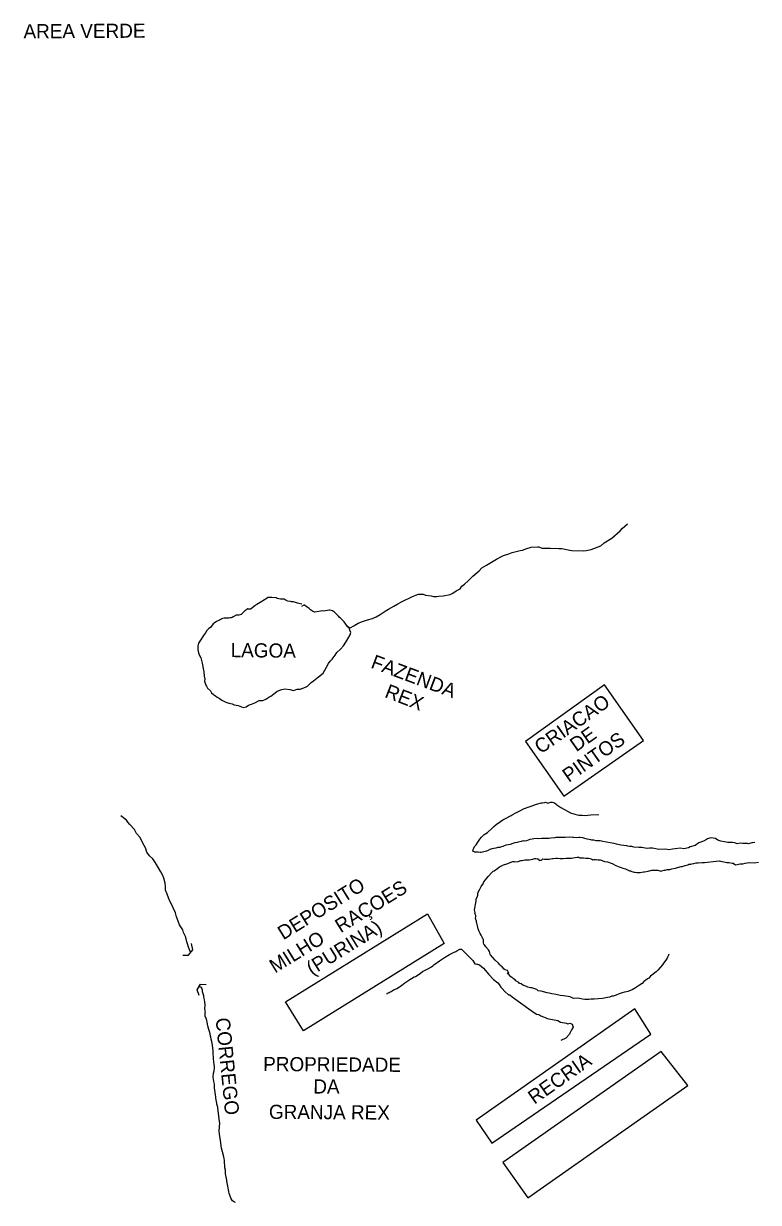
# Model space of a CAD drawing. Extents: x 325899 to 363134, y 7578590 to 7592502.
# Drawn here: x 339067.3 to 339275, y 7582028.3 to 7582361.5 of the extents above; entities that cross this region are included whole.
import ezdxf

# ---------------------------------------------------------------- set-up
doc = ezdxf.new("R2010")
doc.units = 0
for name, color, linetype in [('EDIFEXISTENT', 7, 'Continuous'), ('EDIFIDENTIF', 7, 'Continuous'), ('EDIFOBRAEXIS', 7, 'Continuous')]:
    doc.layers.add(name, color=color, linetype=linetype)

msp = doc.modelspace()

# ---------------------------------------------------------------- linework, layer by layer
at = {"layer": 'EDIFEXISTENT'}
for p, q in [((339231.45, 7582174.59), (339209.14, 7582158.63)), ((339242.46, 7582158.88), (339231.45, 7582174.59)), ((339209.14, 7582158.63), (339220.01, 7582143.13)), ((339220.01, 7582143.13), (339242.46, 7582158.88)), ((339141.27, 7582085.01), (339181.42, 7582109.92)), ((339181.42, 7582109.92), (339186.17, 7582101.54)), ((339113.87, 7582098.24), (339115.06, 7582099.76)), ((339115.06, 7582099.76), (339114.68, 7582101.48)), ((339186.17, 7582101.54), (339146.34, 7582076.83)), ((339112.23, 7582098.19), (339113.87, 7582098.24)), ((339116.31, 7582088.39), (339117.31, 7582090.01)), ((339117.31, 7582090.01), (339118.91, 7582089.96)), ((339116.9, 7582086.81), (339116.31, 7582088.39)), ((339146.34, 7582076.83), (339141.27, 7582085.01)), ((339240.02, 7582083.01), (339195.18, 7582051.55)), ((339244.54, 7582075.84), (339240.02, 7582083.01)), ((339199.58, 7582045.05), (339244.54, 7582075.84)), ((339247.52, 7582071.03), (339202.76, 7582039.63)), ((339255.01, 7582061.35), (339247.52, 7582071.03)), ((339209.78, 7582029.63), (339255.01, 7582061.35)), ((339195.18, 7582051.55), (339199.58, 7582045.05)), ((339202.76, 7582039.63), (339209.78, 7582029.63))]:
    msp.add_line(p, q, dxfattribs=at)
at = {"layer": 'EDIFOBRAEXIS'}
for points in [[(339158.77, 7582191.23), (339159.32, 7582190.71), (339159.6, 7582190.71), (339160.6, 7582191.33), (339160.88, 7582191.51), (339161.85, 7582192.08), (339163.02, 7582192.53), (339164.5, 7582192.99), (339165.93, 7582193.41), (339166.9, 7582193.83), (339168.03, 7582194.48), (339169.49, 7582195.48), (339170.41, 7582196), (339171.87, 7582196.88), (339173.09, 7582197.55), (339174.04, 7582198.05), (339175.04, 7582198.55), (339176.24, 7582199.14), (339177.16, 7582199.56), (339178.18, 7582199.99), (339178.87, 7582200.21), (339180.21, 7582200.24), (339180.82, 7582199.96), (339182.5, 7582199.76), (339183.08, 7582199.6), (339184.04, 7582199.54), (339184.55, 7582199.66), (339185.88, 7582199.75), (339187.86, 7582200.16), (339188.55, 7582200.56), (339189.53, 7582201.16), (339190.62, 7582201.73), (339191.17, 7582202.54), (339191.88, 7582203.06), (339192.94, 7582204.02), (339193.94, 7582205.02), (339194.27, 7582205.37), (339195.5, 7582206.33), (339196.04, 7582206.8), (339196.81, 7582207.68), (339198.12, 7582208.41), (339200.91, 7582210.1), (339202.34, 7582210.93), (339202.93, 7582211.18), (339204.43, 7582211.62), (339205.4, 7582212.04), (339207.64, 7582212.55), (339208.26, 7582212.69), (339209.53, 7582213.14), (339210.42, 7582213.46), (339210.7, 7582213.53), (339212.61, 7582213.64), (339212.87, 7582213.58), (339213.75, 7582213.27), (339215.73, 7582213.27), (339216.24, 7582213.22), (339218.58, 7582213.19), (339219.42, 7582213.15), (339221.65, 7582212.72), (339222.21, 7582212.59), (339225.51, 7582212.48), (339226.27, 7582212.57), (339227.68, 7582212.91), (339230.41, 7582213.9), (339231.41, 7582214.73), (339233.5, 7582216.08), (339235.92, 7582218.16), (339236.43, 7582218.79), (339237.95, 7582220.14)], [(339145.92, 7582197.37), (339144.71, 7582197.66), (339144.12, 7582197.87), (339143.52, 7582198.05), (339143.01, 7582198.11), (339142.75, 7582198.19), (339141.99, 7582198.3), (339141.46, 7582198.48), (339140.91, 7582198.82), (339139.84, 7582198.83), (339138.98, 7582199.04), (339138.67, 7582199.17), (339137.4, 7582199.34), (339136.41, 7582199.33), (339135.62, 7582198.8), (339135.36, 7582198.63), (339134.16, 7582197.9), (339133.16, 7582197.35), (339132.86, 7582197.1), (339132.6, 7582196.93), (339132.27, 7582196.7), (339131.62, 7582196.05), (339131.37, 7582196.03), (339130.86, 7582196.01), (339130.61, 7582196.06), (339130.05, 7582195.68), (339129.79, 7582195.51), (339129.25, 7582194.93), (339128.74, 7582194.5), (339128.15, 7582194.33), (339127.59, 7582194.26), (339127.31, 7582194.27), (339126.72, 7582193.94), (339126.19, 7582193.67), (339125.93, 7582193.57), (339125.62, 7582193.52), (339125.32, 7582193.47), (339124.73, 7582193.48), (339124, 7582193.49), (339123.49, 7582193.34), (339122.93, 7582193.12), (339122.67, 7582192.89), (339121.78, 7582192.47), (339121.11, 7582192.02), (339120.83, 7582191.9), (339120.13, 7582190.86), (339119.59, 7582190.51), (339118.95, 7582189.91), (339118.74, 7582189.38), (339118.33, 7582188.82), (339117.89, 7582188.27), (339117.45, 7582187.51), (339117.24, 7582187.21), (339116.7, 7582186.4), (339116.52, 7582185.59), (339116.48, 7582184.63), (339116.67, 7582183.63), (339116.92, 7582183.07), (339117.34, 7582182.28), (339117.54, 7582181.49), (339117.71, 7582180.7), (339118.14, 7582178.79), (339118.24, 7582178.25), (339118.33, 7582177.03), (339118.45, 7582176.19), (339118.41, 7582175.61), (339118.81, 7582174.56), (339118.96, 7582174.28), (339119.23, 7582173.69), (339120.06, 7582172.9), (339120.39, 7582172.38), (339120.94, 7582171.89), (339121.47, 7582171.51), (339121.97, 7582171.17), (339122.55, 7582170.81), (339123.31, 7582170.29), (339123.84, 7582169.96), (339124.4, 7582169.72), (339125.23, 7582169.43), (339126.22, 7582169.27), (339126.8, 7582169.01), (339127.94, 7582168.74), (339129.29, 7582168.24), (339130.13, 7582168.36), (339130.87, 7582168.86), (339131.71, 7582169.13), (339132.58, 7582169.56), (339133.88, 7582170.23), (339134.85, 7582170.19), (339135.74, 7582170.54), (339136.59, 7582171.14), (339137.12, 7582171.46), (339138.38, 7582172.39), (339138.97, 7582172.84), (339140.24, 7582173.26), (339141.09, 7582173.5), (339142.56, 7582173.26), (339143.55, 7582172.97), (339144.62, 7582173.36), (339145.43, 7582173.38), (339146.96, 7582174), (339147.47, 7582174.27), (339148.53, 7582175.25), (339149.19, 7582175.78), (339150.6, 7582176.91), (339151.91, 7582177.93), (339152.87, 7582179.65), (339153.41, 7582180.61), (339153.95, 7582181.27), (339154.44, 7582181.87), (339155.32, 7582183.03), (339155.84, 7582183.76), (339156.84, 7582184.67), (339157.71, 7582185.65), (339158.39, 7582186.63), (339158.9, 7582187.62), (339159.6, 7582188.78), (339159.79, 7582189.41), (339159.52, 7582190.1), (339159.27, 7582190.69), (339158.77, 7582191.23), (339158.39, 7582191.76), (339157.84, 7582192.41), (339157.39, 7582192.89), (339156.93, 7582193.38), (339156.46, 7582193.77), (339156.28, 7582194.05), (339155.58, 7582194.64), (339155.15, 7582195.18), (339154.57, 7582195.54), (339153.94, 7582195.7), (339153.68, 7582195.73), (339153.12, 7582195.63), (339152.03, 7582195.44), (339151.65, 7582195.52), (339150.75, 7582195.33), (339150.12, 7582195.21), (339149.46, 7582195.19), (339148.93, 7582195.45), (339148.4, 7582195.84), (339147.89, 7582196.3), (339147.14, 7582196.77), (339146.68, 7582197.13), (339146.43, 7582197.16), (339145.81, 7582196.76)], [(339273.96, 7582130.06), (339273.33, 7582129.96), (339273.07, 7582129.97), (339272.18, 7582129.72), (339271.92, 7582129.75), (339270.93, 7582129.76), (339270.55, 7582129.79), (339269.82, 7582129.88), (339268.93, 7582129.68), (339268.27, 7582129.94), (339267.68, 7582130.05), (339266.29, 7582130.02), (339265.35, 7582130.26), (339264.33, 7582130.42), (339263.47, 7582130.68), (339262.87, 7582131.15), (339261.47, 7582131.37), (339260.53, 7582131.12), (339260.27, 7582130.92), (339259.45, 7582130.42), (339258.08, 7582129.93), (339257.05, 7582129.25), (339255.72, 7582128.79), (339255.21, 7582128.59), (339253.91, 7582128.25), (339252.85, 7582128.44), (339251.47, 7582128.22), (339250.66, 7582128.21), (339249.69, 7582128.01), (339248.81, 7582128.15), (339246.8, 7582128.1), (339245.02, 7582128.45), (339244.21, 7582128.45), (339243.65, 7582128.38), (339242.96, 7582128.49), (339242, 7582128.61), (339241.19, 7582128.69), (339239.79, 7582128.73), (339239.18, 7582128.97), (339238.55, 7582128.97), (339238.01, 7582129), (339237.73, 7582129.11), (339236.11, 7582129.28), (339234.84, 7582129.57), (339234.16, 7582129.76), (339233.07, 7582130), (339231.98, 7582130.11), (339230.99, 7582130.38), (339230.58, 7582130.46), (339230.2, 7582130.51), (339229.72, 7582130.52), (339229.11, 7582130.55), (339228.45, 7582130.71), (339227.84, 7582130.72), (339227.59, 7582130.77), (339226.52, 7582131.04), (339225.91, 7582131.22), (339225.36, 7582131.41), (339224.52, 7582131.44), (339224.21, 7582131.44), (339223.68, 7582131.35), (339222.77, 7582131.43), (339222.49, 7582131.51), (339221.62, 7582131.55), (339220.35, 7582131.51), (339219.39, 7582131.47), (339218.7, 7582131.45), (339218.39, 7582131.48), (339217.68, 7582131.44), (339217.38, 7582131.42), (339216.33, 7582131.25), (339215.75, 7582131.23), (339214.88, 7582131.19), (339214.3, 7582131.2), (339213.79, 7582131.23), (339212.9, 7582131.09), (339212.39, 7582131.14), (339211.53, 7582131.07), (339210.97, 7582130.98), (339210.31, 7582130.91), (339209.44, 7582130.56), (339208.78, 7582130.44), (339208.5, 7582130.5), (339207.91, 7582130.38), (339207.1, 7582130.11), (339206.74, 7582130.06), (339206.15, 7582129.96), (339205.59, 7582129.82), (339204.75, 7582129.5), (339204.24, 7582129.43), (339203.6, 7582129.26), (339202.74, 7582128.96), (339202.1, 7582128.74), (339201.84, 7582128.64), (339201.31, 7582128.65), (339200.72, 7582128.47), (339200.16, 7582128.4), (339199.6, 7582128.28), (339199.07, 7582128.09), (339198.4, 7582127.74), (339198.15, 7582127.61), (339197, 7582127.32), (339196.62, 7582127.22), (339196.34, 7582127.23), (339195.75, 7582127.28), (339194.81, 7582127.29), (339194.21, 7582127.58), (339194.37, 7582128.06), (339194.52, 7582128.49), (339194.73, 7582128.92), (339195.17, 7582129.4), (339195.66, 7582130.16), (339196.25, 7582130.96), (339196.74, 7582131.54), (339197.44, 7582132.32), (339198.36, 7582132.92), (339199.64, 7582134.05), (339200.21, 7582134.58), (339200.85, 7582135.11), (339202.1, 7582135.98), (339202.77, 7582136.43), (339203.46, 7582136.86), (339205.12, 7582137.7), (339205.4, 7582137.88), (339206.42, 7582138.48), (339206.99, 7582138.77), (339207.68, 7582139.07), (339208.57, 7582139.55), (339209.92, 7582140.06), (339210.76, 7582140.28), (339212.27, 7582140.88), (339213.67, 7582141.27), (339213.93, 7582141.29), (339214.49, 7582141.39), (339214.79, 7582141.43), (339215.45, 7582141.2), (339216.32, 7582141.47), (339216.7, 7582141.49), (339217.36, 7582141.3), (339217.76, 7582140.89), (339218.01, 7582140.74), (339219.12, 7582139.96), (339220.99, 7582138.87), (339221.83, 7582138.48), (339223.12, 7582138.06), (339224.18, 7582137.75), (339225.17, 7582137.76), (339226.09, 7582137.73), (339226.77, 7582137.74), (339227.61, 7582137.89), (339229.88, 7582138.01)], [(339114.43, 7582099.04), (339113.83, 7582100.43), (339113.66, 7582101.12), (339113.39, 7582102.01), (339113.22, 7582102.85), (339113.07, 7582103.51), (339112.47, 7582104.59), (339112.25, 7582105.38), (339111.35, 7582106.76), (339110.91, 7582107.78), (339110.46, 7582109.03), (339110.2, 7582110.18), (339109.55, 7582111.63), (339109.11, 7582112.6), (339108.53, 7582113.7), (339108.24, 7582114.39), (339107.84, 7582115.44), (339107.42, 7582116.54), (339107.41, 7582117.6), (339107.24, 7582118.52), (339106.93, 7582120.02), (339106.65, 7582120.76), (339106.08, 7582121.76), (339105.13, 7582123.4), (339104.51, 7582124.27), (339103.76, 7582125.45), (339102.88, 7582126.32), (339102.1, 7582127.37), (339101.68, 7582128.54), (339100.96, 7582129.87), (339100.24, 7582131.43), (339099.19, 7582132.64), (339098.59, 7582133.69), (339097.33, 7582135.17), (339096.7, 7582135.82), (339096.38, 7582136.33), (339094.72, 7582137.62)], [(339249.67, 7582098.46), (339249.57, 7582098.2), (339249.28, 7582097.65), (339249.13, 7582097.37), (339248.84, 7582096.81), (339248.17, 7582095.96), (339247.81, 7582095.45), (339246.55, 7582093.99), (339246.11, 7582093.54), (339244.5, 7582092.29), (339243.98, 7582091.76), (339243.62, 7582091.51), (339243.16, 7582091.13), (339242.6, 7582090.81), (339242.06, 7582090.23), (339241.39, 7582089.75), (339240.24, 7582088.98), (339239.25, 7582088.45), (339238.07, 7582087.96), (339237.66, 7582087.86), (339237.1, 7582087.77), (339236.49, 7582087.6), (339235.62, 7582087.3), (339234.73, 7582086.95), (339233.91, 7582086.66), (339233.53, 7582086.59), (339232.87, 7582086.36), (339232.28, 7582086.24), (339230.88, 7582085.95), (339229.66, 7582085.84), (339228.57, 7582085.78), (339227.63, 7582085.76), (339226.99, 7582085.72), (339226.15, 7582085.65), (339225.9, 7582085.7), (339225.24, 7582085.79), (339224.38, 7582085.92), (339223.74, 7582086.06), (339222.7, 7582085.99), (339221.76, 7582086.41), (339221.18, 7582086.57), (339220.49, 7582086.6), (339219.86, 7582086.68), (339218.95, 7582086.85), (339217.81, 7582087.06), (339216.59, 7582087.28), (339215.78, 7582087.47), (339215.22, 7582087.55), (339213.57, 7582088.02), (339212.73, 7582088.11), (339212.31, 7582088.5), (339212.03, 7582088.63), (339211.5, 7582088.84), (339210.89, 7582088.97), (339210.58, 7582089.02), (339209.77, 7582089.13), (339209.22, 7582089.42), (339208.41, 7582089.78), (339207.95, 7582090.07), (339207.39, 7582090.25), (339207.25, 7582090.53), (339206.44, 7582090.95), (339206.24, 7582091.21), (339205.78, 7582091.49), (339205.56, 7582091.75), (339204.95, 7582092.06), (339204.5, 7582092.62), (339203.94, 7582093.16), (339204.45, 7582093.13), (339204.03, 7582093.9), (339203.37, 7582094.11), (339203.07, 7582094.29), (339202.54, 7582094.93), (339202.29, 7582095.14), (339201.84, 7582095.52), (339201.46, 7582095.91), (339200.55, 7582096.83), (339199.25, 7582098.32), (339199.07, 7582098.65), (339199.03, 7582098.91), (339198.95, 7582099.24), (339198.63, 7582099.68), (339197.93, 7582100.6), (339197.5, 7582101.09), (339197.38, 7582101.34), (339197.23, 7582101.7), (339197.29, 7582102.61), (339197.09, 7582102.87), (339196.89, 7582103.28), (339196.59, 7582103.82), (339196.29, 7582104.35), (339195.99, 7582104.94), (339195.75, 7582105.68), (339195.53, 7582106.5), (339195.38, 7582107.29), (339195.28, 7582107.54), (339195.26, 7582107.87), (339194.96, 7582108.56), (339195.05, 7582109.14), (339195.08, 7582109.42), (339194.85, 7582109.99), (339194.86, 7582110.24), (339194.74, 7582111.03), (339195.15, 7582113.46), (339195.2, 7582114.02), (339195.52, 7582114.91), (339195.65, 7582115.16), (339195.68, 7582115.67), (339195.81, 7582116.18), (339195.99, 7582116.45), (339196.3, 7582117.06), (339196.59, 7582117.59), (339196.79, 7582117.87), (339197.21, 7582118.42), (339197.37, 7582118.93), (339197.83, 7582119.48), (339198.58, 7582120.47), (339199.68, 7582121.7), (339200.02, 7582121.95), (339200.3, 7582122.07), (339201.35, 7582122.82), (339201.78, 7582123.18), (339202.93, 7582123.75), (339203.88, 7582124.04), (339205.51, 7582124.66), (339205.82, 7582124.68), (339206.12, 7582124.63), (339207.04, 7582124.69), (339207.85, 7582124.99), (339208.21, 7582125.01), (339208.92, 7582125.13), (339209.2, 7582125.13), (339209.46, 7582125.18), (339210.17, 7582125.19), (339210.68, 7582125.29), (339211.19, 7582125.33), (339211.8, 7582125.53), (339212.05, 7582125.53), (339212.41, 7582125.47), (339212.76, 7582125.42), (339212.99, 7582124.96), (339213.37, 7582125.06), (339213.65, 7582125.1), (339214.03, 7582125.43), (339214.51, 7582125.35), (339214.85, 7582125.32), (339215.79, 7582125.31), (339216.24, 7582125.43), (339216.73, 7582125.53), (339216.98, 7582125.55), (339217.67, 7582125.59), (339218.15, 7582125.61), (339218.91, 7582125.5), (339219.8, 7582125.52), (339220.59, 7582125.61), (339221.66, 7582125.65), (339222.09, 7582125.65), (339222.6, 7582125.72), (339223.19, 7582125.81), (339223.77, 7582125.88), (339224.15, 7582125.88), (339224.53, 7582125.77), (339225.27, 7582125.74), (339225.52, 7582125.69), (339226.18, 7582125.6), (339226.97, 7582125.59), (339227.38, 7582125.56), (339227.86, 7582125.36), (339228.14, 7582125.2), (339228.47, 7582125.25), (339228.8, 7582125.24), (339229.13, 7582125.19), (339229.38, 7582125.21), (339229.71, 7582125.13), (339230.24, 7582125.13), (339230.83, 7582124.97), (339231.46, 7582124.73), (339232.35, 7582124.59), (339233.39, 7582124.2), (339233.64, 7582124.12), (339234.65, 7582123.53), (339235.61, 7582123.21), (339236.19, 7582122.95), (339236.62, 7582122.79), (339237.41, 7582122.58), (339237.81, 7582122.42), (339238.52, 7582122.06), (339238.85, 7582122.01), (339239.15, 7582121.83), (339239.46, 7582121.75), (339239.81, 7582121.67), (339240.12, 7582121.64), (339240.63, 7582121.61), (339241.52, 7582121.62), (339242.46, 7582121.76), (339242.81, 7582121.79), (339243.78, 7582122), (339244.04, 7582122.05), (339244.57, 7582122.17), (339244.83, 7582122.2), (339245.26, 7582122.27), (339246.05, 7582122.26), (339246.58, 7582122.2), (339247.39, 7582121.96), (339247.67, 7582122.09), (339248.33, 7582122.23), (339248.61, 7582122.28), (339249.22, 7582122.38), (339249.91, 7582122.47), (339250.17, 7582122.49), (339250.5, 7582122.59), (339251.49, 7582122.83), (339252.1, 7582123), (339253.17, 7582123.25), (339253.43, 7582123.3), (339254.27, 7582123.54), (339254.98, 7582123.79), (339255.32, 7582123.91), (339255.85, 7582123.98), (339256.16, 7582124.05), (339256.72, 7582124.12), (339257.35, 7582124.32), (339257.89, 7582124.34), (339259.11, 7582124.45), (339259.69, 7582124.4), (339263.03, 7582124.77), (339263.97, 7582124.83), (339264.27, 7582124.8), (339265.16, 7582124.62), (339265.69, 7582124.51), (339266.05, 7582124.45), (339266.73, 7582124.37), (339267.52, 7582124.23), (339267.8, 7582124.23), (339268.5, 7582123.79), (339269.8, 7582124.01), (339270.06, 7582124.03), (339270.59, 7582124.02), (339271.18, 7582124.19), (339272.32, 7582124.36), (339273.77, 7582124.27), (339274.97, 7582124.48)], [(339170.03, 7582087.23), (339170.03, 7582087.49), (339170.36, 7582087.58), (339170.62, 7582087.66), (339170.92, 7582087.81), (339171.18, 7582087.93), (339171.49, 7582088.18), (339171.79, 7582088.43), (339172.35, 7582088.58), (339172.79, 7582088.8), (339173.56, 7582089.28), (339173.84, 7582089.48), (339174.58, 7582090), (339174.99, 7582090.43), (339175.56, 7582090.81), (339176.4, 7582091.33), (339176.94, 7582091.63), (339177.65, 7582092.05), (339178.06, 7582092.2), (339178.8, 7582092.68), (339179.44, 7582093.13), (339180.06, 7582093.6), (339180.93, 7582094.05), (339181.67, 7582094.47), (339182.54, 7582094.9), (339182.97, 7582095.22), (339183.26, 7582095.47), (339184.79, 7582096.6), (339185.38, 7582097.03), (339186.23, 7582097.55), (339187.15, 7582098.1), (339187.69, 7582098.37), (339188.78, 7582098.95), (339189.42, 7582099.29), (339189.71, 7582099.44), (339190.57, 7582099.89), (339191.08, 7582099.94), (339194.25, 7582096.75), (339194.77, 7582095.78), (339195.33, 7582095.7), (339195.61, 7582095.64), (339196.14, 7582095.46), (339197.28, 7582094.51), (339198.73, 7582092.76), (339200.06, 7582091.35), (339201.27, 7582090.37), (339201.72, 7582089.91), (339202.17, 7582089.14), (339202.55, 7582088.78), (339203.28, 7582087.99), (339204.36, 7582087.01), (339204.69, 7582087), (339205.4, 7582086.46), (339210.69, 7582082.62), (339212.2, 7582081.51), (339212.89, 7582081.4), (339213.47, 7582081.04), (339214.2, 7582080.77), (339214.68, 7582080.59), (339215.24, 7582080.33), (339218.23, 7582079.76), (339219.02, 7582079.27), (339220.74, 7582079.03), (339221.12, 7582078.82), (339221.78, 7582079.01), (339222.29, 7582078.73), (339222.56, 7582077.91), (339222.17, 7582077.08), (339221.7, 7582076.14), (339221.55, 7582075.87), (339220.52, 7582074.78), (339219.16, 7582074.09)], [(339127.14, 7582028.33), (339126.89, 7582028.44), (339126.36, 7582028.77), (339126.13, 7582029.08), (339125.91, 7582029.34), (339125.81, 7582029.59), (339125.39, 7582030.82), (339125.29, 7582031.38), (339125.2, 7582031.89), (339125.13, 7582032.45), (339124.72, 7582034.36), (339124.69, 7582034.61), (339124.38, 7582036.45), (339124.29, 7582037.46), (339124.12, 7582038.07), (339124.02, 7582040.16), (339124, 7582040.74), (339123.75, 7582041.59), (339123.22, 7582043.68), (339122.91, 7582045.84), (339122.68, 7582047.65), (339122.58, 7582048.56), (339122.71, 7582050.7), (339122.59, 7582051.79), (339122.48, 7582052.76), (339122.2, 7582054.97), (339122.15, 7582055.28), (339121.9, 7582056.09), (339121.86, 7582056.4), (339121.62, 7582057.82), (339121.6, 7582058.13), (339121.5, 7582058.74), (339121.46, 7582059.38), (339121.29, 7582060.17), (339121.27, 7582060.6), (339121.25, 7582060.85), (339121.26, 7582061.74), (339121.06, 7582062.53), (339120.91, 7582063.14), (339120.87, 7582063.7), (339120.96, 7582064.87), (339121.12, 7582065.51), (339121.23, 7582066.24), (339121.23, 7582066.77), (339121.14, 7582067.44), (339121.02, 7582068), (339120.95, 7582069.07), (339120.91, 7582069.35), (339120.89, 7582070.34), (339120.89, 7582070.59), (339120.85, 7582071.15), (339120.76, 7582072.04), (339120.66, 7582072.7), (339120.54, 7582073.31), (339120.47, 7582073.82), (339120.33, 7582074.46), (339120.18, 7582075.07), (339120.06, 7582075.35), (339119.96, 7582075.94), (339119.82, 7582076.6), (339119.65, 7582077.19), (339119.45, 7582077.9), (339119.26, 7582078.69), (339119.11, 7582079.38), (339119.04, 7582079.79), (339118.84, 7582080.35), (339118.62, 7582080.99), (339118.63, 7582081.95), (339118.66, 7582082.23), (339118.61, 7582082.51), (339118.49, 7582083.1), (339118.55, 7582084.04), (339118.54, 7582085.08), (339118.44, 7582085.46), (339118.29, 7582086.07), (339118.25, 7582086.48), (339118.18, 7582086.76), (339117.88, 7582087.83), (339117.84, 7582088.31), (339117.61, 7582088.87), (339117.49, 7582089.16), (339116.94, 7582089.3)]]:
    msp.add_lwpolyline(points, dxfattribs=at)

# ---------------------------------------------------------------- texts
at = {"layer": 'EDIFIDENTIF'}
for s, rotation, p in [('AREA VERDE', 0.3142, (339067.25, 7582357.32)), ('LAGOA', 359.3711, (339125.78, 7582182.45)), ('FAZENDA', 339.5914, (339165.17, 7582179.52)), ('REX', 338.7222, (339169.08, 7582171.22)), ('CRIACAO', 35.0486, (339213.44, 7582154.94)), ('DE', 35.0486, (339223.49, 7582155.55)), ('PINTOS', 35.0486, (339221.36, 7582146.87)), ('DEPOSITO', 31.8135, (339140.67, 7582102.39)), ('RAÇOES', 31.8135, (339156.89, 7582104.36)), ('(PURINA)', 31.8135, (339148.78, 7582092.41)), ('MILHO', 31.8135, (339138.34, 7582092.98)), ('CORREGO', 275.7274, (339121.53, 7582080.36)), ('PROPRIEDADE', 359.6587, (339134.98, 7582065.46)), ('RECRIA', 35.0486, (339211.64, 7582055.91)), (' DA ', 359.6587, (339147.65, 7582059.13)), ('GRANJA REX', 359.6587, (339136.6, 7582051.94))]:
    msp.add_text(s, height=4, rotation=rotation, dxfattribs=at).set_placement(p)

doc.saveas('drawing.dxf')
